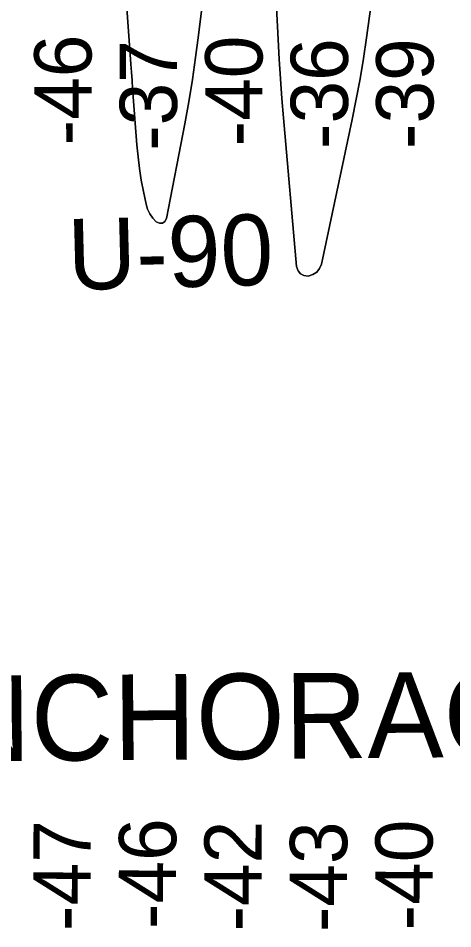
# Model space of a CAD drawing. Extents: x 3313447 to 3351316, y 703786 to 729172.
# Drawn here: x 3323196 to 3323704, y 719501 to 720566 of the extents above; entities that cross this region are included whole.
import ezdxf

# ---------------------------------------------------------------- set-up
doc = ezdxf.new("R2010")
doc.units = 0
for name, color, linetype in [('V-RIVR-RANG', 7, 'Continuous'), ('V-RIVR-RANG-IDEN', 7, 'Continuous'), ('V-TOPO-DPTH', 7, 'Continuous'), ('V-TOPO-GNAM-IDEN', 7, 'Continuous'), ('V-TOPO-MINR', 7, 'Continuous')]:
    doc.layers.add(name, color=color, linetype=linetype)

msp = doc.modelspace()

# ---------------------------------------------------------------- linework, layer by layer
at = {"layer": 'V-TOPO-DPTH'}
for points in [[(3323291.7, 721016), (3323327.5, 720512.2), (3323328.2, 720502.7), (3323328.9, 720493.1), (3323329.6, 720483.6), (3323330.3, 720474), (3323334.6, 720417.5), (3323335.9, 720403.8), (3323337.6, 720390.1), (3323339.7, 720376.5), (3323342.3, 720363), (3323345.3, 720348.4), (3323347.1, 720342.5), (3323349.6, 720337), (3323353.1, 720332), (3323357.3, 720327.4), (3323361.1, 720326), (3323364.4, 720326), (3323367.1, 720328), (3323369.2, 720331.4), (3323390.6, 720442.3), (3323395.2, 720468.1), (3323399.6, 720494), (3323403.3, 720520), (3323406.8, 720546), (3323417.5, 720635)], [(3323417.5, 720635), (3323406.8, 720546), (3323403.3, 720520), (3323399.6, 720494), (3323395.2, 720468.1), (3323390.6, 720442.3), (3323369.2, 720331.4), (3323367.1, 720328), (3323364.4, 720326), (3323361.1, 720326), (3323357.3, 720327.4), (3323353.1, 720332), (3323349.6, 720337), (3323347.1, 720342.5), (3323345.3, 720348.4), (3323342.3, 720363), (3323339.7, 720376.5), (3323337.6, 720390.1), (3323335.9, 720403.8), (3323334.6, 720417.5), (3323330.3, 720474), (3323329.6, 720483.6), (3323328.9, 720493.1), (3323328.2, 720502.7), (3323327.5, 720512.2), (3323291.7, 721016)], [(3323482.3, 720881.2), (3323499.7, 720540.7), (3323501, 720517.8), (3323502.5, 720494.9), (3323504.2, 720472), (3323506.1, 720449.1), (3323521.3, 720275.3), (3323523.1, 720270.4), (3323525.8, 720266.8), (3323530, 720264.9), (3323535.1, 720264.1), (3323540.5, 720265.9), (3323545, 720268.7), (3323548.2, 720272.9), (3323550.4, 720278.1), (3323586.4, 720447.2), (3323591.2, 720471), (3323595.6, 720494.8), (3323599.6, 720518.8), (3323603.1, 720542.7), (3323626.4, 720712)], [(3323626.4, 720712), (3323603.1, 720542.7), (3323599.6, 720518.8), (3323595.6, 720494.8), (3323591.2, 720471), (3323586.4, 720447.2), (3323550.4, 720278.1), (3323548.2, 720272.9), (3323545, 720268.7), (3323540.5, 720265.9), (3323535.1, 720264.1), (3323530, 720264.9), (3323525.8, 720266.8), (3323523.1, 720270.4), (3323521.3, 720275.3), (3323506.1, 720449.1), (3323504.2, 720472), (3323502.5, 720494.9), (3323501, 720517.8), (3323499.7, 720540.7), (3323482.3, 720881.2)]]:
    msp.add_lwpolyline(points, dxfattribs=at)
at = {"layer": 'V-TOPO-MINR'}
for points in [[(3323291.7, 721016), (3323327.5, 720512.2), (3323328.2, 720502.7), (3323328.9, 720493.1), (3323329.6, 720483.6), (3323330.3, 720474), (3323334.6, 720417.5), (3323335.9, 720403.8), (3323337.6, 720390.1), (3323339.7, 720376.5), (3323342.3, 720363), (3323345.3, 720348.4), (3323347.1, 720342.5), (3323349.6, 720337), (3323353.1, 720332), (3323357.3, 720327.4), (3323361.1, 720326), (3323364.4, 720326), (3323367.1, 720328), (3323369.2, 720331.4), (3323390.6, 720442.3), (3323395.2, 720468.1), (3323399.6, 720494), (3323403.3, 720520), (3323406.8, 720546), (3323417.5, 720635)], [(3323482.3, 720881.2), (3323499.7, 720540.7), (3323501, 720517.8), (3323502.5, 720494.9), (3323504.2, 720472), (3323506.1, 720449.1), (3323521.3, 720275.3), (3323523.1, 720270.4), (3323525.8, 720266.8), (3323530, 720264.9), (3323535.1, 720264.1), (3323540.5, 720265.9), (3323545, 720268.7), (3323548.2, 720272.9), (3323550.4, 720278.1), (3323586.4, 720447.2), (3323591.2, 720471), (3323595.6, 720494.8), (3323599.6, 720518.8), (3323603.1, 720542.7), (3323626.4, 720712)]]:
    msp.add_lwpolyline(points, dxfattribs=at)

# ---------------------------------------------------------------- texts
at = {"layer": 'V-RIVR-RANG'}
for s, rotation, p in [('-46', 90.0155, (3323281.5, 720417.1)), ('-40', 90.0155, (3323481.5, 720415.9)), ('-37', 90.0155, (3323381.5, 720410.6)), ('-36', 90.0155, (3323581.5, 720412.8)), ('-39', 90.0155, (3323681.5, 720412.8)), ('-46', 89.798, (3323380.2, 719500.2)), ('-40', 89.798, (3323680.2, 719498.6)), ('-47', 89.798, (3323280.2, 719497.9)), ('-42', 89.798, (3323480.2, 719497.3)), ('-43', 89.798, (3323580.2, 719496.5))]:
    msp.add_text(s, height=67, rotation=rotation, dxfattribs=at).set_placement(p)
at = {"layer": 'V-RIVR-RANG-IDEN'}
msp.add_text('U-90', height=83, rotation=1.5066, dxfattribs=at).set_placement((3323254.6, 720247.7))
at = {"layer": 'V-TOPO-GNAM-IDEN'}
msp.add_text('ANCHORAGE LDG.', height=100, rotation=0.462, dxfattribs=at).set_placement((3323025, 719695.6))

doc.saveas('drawing.dxf')
